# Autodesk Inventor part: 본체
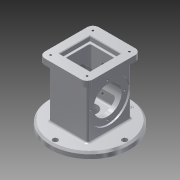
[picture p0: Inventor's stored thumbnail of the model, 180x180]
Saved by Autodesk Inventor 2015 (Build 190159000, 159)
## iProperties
Created: 2019-08
Part Number: 본체
Material: 알루미늄 6061
Document SubType Name: Modeling
Designer: now
Density: 2.7 g/cm^3
Appearance: 알루미늄 - 평지
Mass: 1041.24 g
Surface Area: 795.125 cm^2
Volume: 385.644 cm^3
Author: now
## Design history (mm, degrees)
sketch "스케치1"
  geometry: C1 r 67.5 at (0, 0); 1 further point
  constraints: 1 centre point, 1 coincident
  dimensions: "d0" = 135 diameter of C1
extrude "돌출1" new body sketch "스케치1" distance "d1" = 10; taper "d2" = 0 deg
sketch "스케치2"
  geometry: L1 (-33, 37)-(33, 37); L2 (33, 37)-(33, -37); L3 (33, -37)-(-33, -37); L4 (-33, -37)-(-33, 37); L5 (-33, 37)-(33, -37); L6 (33, 37)-(-33, -37); C1 r 67.5 at (0, 0) reference
  constraints: 12 end point, 2 midpoint, 2 parallel, 1 horizontal, 1 perpendicular
  dimensions: "d3" = 66 distance of L1.start L1.end; "d4" = 74 distance of L3.end L1.start
extrude "돌출2" join sketch "스케치2" distance "d5" = 88; taper "d6" = 0 deg
sketch "스케치3"
  geometry: L1 (-41, 46)-(41, 46); L2 (41, 46)-(41, -46); L3 (41, -46)-(-41, -46); L4 (-41, -46)-(-41, 46); L5 (-41, 46)-(41, -46); L6 (41, 46)-(-41, -46); 1 further point
  constraints: 12 end point, 2 midpoint, 2 parallel, 1 horizontal, 1 perpendicular
  dimensions: "d7" = 92 distance of L3.end L1.start; "d8" = 82 distance of L1.start L1.end
extrude "돌출3" join sketch "스케치3" distance "d9" = 10; taper "d10" = 0 deg
fillet "모깎기1" dims "d11" = 10
fillet "모깎기2" dims "d12" = 3
sketch "스케치4"
  geometry: L1 (10, -33.5)-(10, 101.5) reference; C1 r 35 at (-44, 34); 1 further point
  constraints: 1 centre point, 1 horizontal alignment
  dimensions: "d13" = 70 diameter of C1; "d14" = 54 distance from line of L1 C1.centre
extrude "돌출4" cut sketch "스케치4" distance "d15" = 3; taper "d16" = 0 deg
sketch "스케치5"
  geometry: C1 r 35 at (0, 0) reference; 1 further point
hole "구멍1" sketch "스케치5" at (0, 0) diameter "d17" = 48; stored, may be unused: countersink angle "d21" = 90 deg, drill point angle "d23" = 118 deg; dims "d18" = 6, "d19" = 4, "d20" = 2, "d22" = 8
sketch "스케치7"
  geometry: L1 (-26, 26)-(26, 26); L2 (26, 26)-(26, -26); L3 (26, -26)-(-26, -26); L4 (-26, -26)-(-26, 26); L5 (-26, 26)-(26, -26); L6 (26, 26)-(-26, -26); 1 further point
  constraints: 12 end point, 2 midpoint, 2 parallel, 1 horizontal, 1 perpendicular
  dimensions: "d35" = 52 distance of L1.start L1.end; "d36" = 52 distance of L1.end L2.end
extrude "돌출5" cut sketch "스케치7" distance "d37" = 8; taper "d38" = 0 deg
sketch "스케치8"
  geometry: L1 (-22, -22)-(22, -22); L2 (22, -22)-(22, 22); L3 (22, 22)-(-22, 22); L4 (-22, 22)-(-22, -22); L5 (-22, -22)-(22, 22); L6 (22, -22)-(-22, 22); 1 further point
  constraints: 12 end point, 2 midpoint, 2 parallel, 1 horizontal, 1 perpendicular
  dimensions: "d39" = 44 distance of L3.end L1.start; "d40" = 44 distance of L2.end L3.end
extrude "돌출6" cut sketch "스케치8" distance "d41" = 74; taper "d42" = 0 deg
chamfer "모따기1" distance "d43" = 1; stored, may be unused: second distance "d44" = 2, angle "d45" = 45 deg
chamfer "모따기2" distance "d46" = 1; stored, may be unused: second distance "d47" = 2, angle "d48" = 45 deg
sketch "스케치9"
  geometry: A1 r 10 centre (31, 36) between (41, 36) and (31, 46) reference; A2 r 10 centre (-31, 36) between (-31, 46) and (-41, 36) reference; A3 r 10 centre (-31, -36) between (-41, -36) and (-31, -46) reference; A4 r 10 centre (31, -36) between (31, -46) and (41, -36) reference; 1 further point
hole "구멍3" sketch "스케치9" at (-31, -36), (31, -36), (31, 36), (-31, 36) diameter "d49" = 3.242; stored, may be unused: countersink angle "d53" = 90 deg, drill point angle "d55" = 118 deg; dims "d50" = 4, "d51" = 4, "d52" = 2, "d54" = 6
sketch "스케치10"
  geometry: C1 r 67.5 at (0, 0) reference; 3 further points
  constraints: 2 horizontal alignment, 1 vertical alignment
  dimensions: "d56" = 59 distance of C1.centre point (-59, 0); "d57" = 59 distance of point (59, 0) C1.centre; "d58" = 59 distance of C1.centre point (0, -59)
hole "구멍4" sketch "스케치10" at (-59, 0), (59, 0), (0, -59) diameter "d60" = 9; stored, may be unused: countersink angle "d64" = 90 deg, drill point angle "d66" = 0 deg; dims "d61" = 4, "d62" = 4, "d63" = 2, "d65" = 6
fillet "모깎기4" dims "d68" = 3
sketch "스케치11"
  geometry: C1 r 67.5 at (0, 0) reference; C2 r 25 at (0, 0)
  constraints: 1 centre point, 1 coincident
  dimensions: "d69" = 50 diameter of C2
extrude "돌출7" cut sketch "스케치11" distance "d70" = 18; taper "d71" = 0 deg
sketch "스케치12"
  geometry: C1 r 25 at (0, 0) reference; C2 r 12.5 at (0, 0)
  constraints: 1 centre point, 1 coincident
  dimensions: "d72" = 25 diameter of C2
extrude "돌출8" cut sketch "스케치12" stored distance "d73" = 18; taper "d74" = 0 deg
fillet "모깎기5" dims "d75" = 3
fillet "모깎기6" dims "d76" = 3
sketch "스케치13"
  geometry: C1 r 24 at (0, 0) reference; 2 further points
  constraints: 1 horizontal alignment
  dimensions: "d77" = 29 distance of C1.centre point (-29, 0)
hole "구멍5" sketch "스케치13" at (-29, 0) diameter "d78" = 3.242; stored, may be unused: countersink angle "d82" = 90 deg, drill point angle "d84" = 118 deg; dims "d79" = 4, "d80" = 4, "d81" = 2, "d83" = 6
sketch "스케치15"
  geometry: L1 (97.5, 10)-(-37.5, 10) reference; 3 further points
  constraints: 2 vertical alignment
  dimensions: "d92" = 43 distance of point (30, -27) point (30, -70); "d93" = 37 distance from line of L1 point (30, -27)
hole "구멍6" sketch "스케치15" at (30, -70), (30, -27) diameter "d94" = 4.917; stored, may be unused: countersink angle "d98" = 90 deg, drill point angle "d100" = 0 deg; dims "d95" = 12, "d96" = 4, "d97" = 2, "d99" = 20
fillet "모깎기7" dims "d101" = 3
chamfer "모따기3" distance "d102" = 3; stored, may be unused: second distance "d103" = 2, angle "d104" = 45 deg
sketch "스케치16"
  geometry: C1 r 4.5 at (-59, 0) reference; C2 r 64.5 at (0, 0) reference; C3 r 4.5 at (0, 59); A1 r 59 centre (0, 0) between (-59, 0) and (0, 59)
  constraints: 2 centre point, 2 point on circle, 1 coincident, 1 vertical alignment, 1 other
  dimensions: "d105" = 9 diameter of C3
feature "엠보싱2" sketch "스케치16" dims "d106" = 0.5, "d107" = 0
fillet "모깎기8" dims "d108" = 3
node "솔리드1"
mirror "대칭1"
pattern_circular "원형 패턴2" dims angle "d86" = 360 deg
mirror "대칭3"
